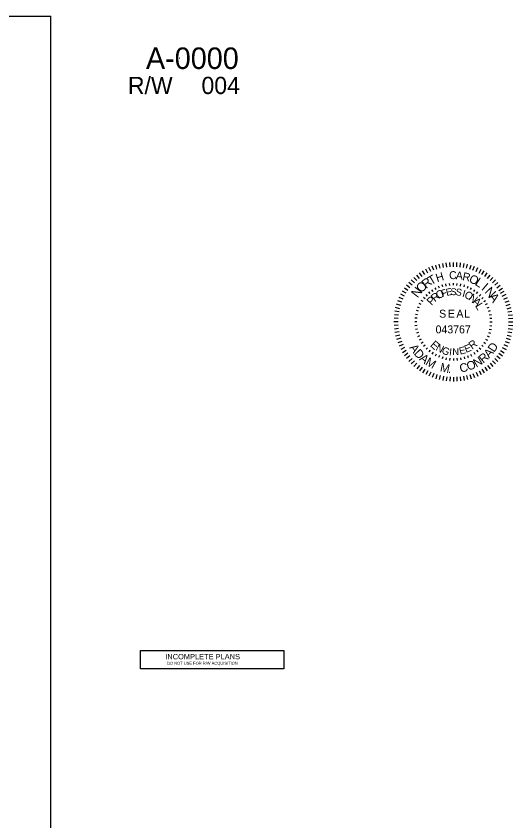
# Model space of a CAD drawing. Extents: x 24 to 2046, y 15 to 1115.
# Drawn here: x 1700 to 2046, y 554 to 1115 of the extents above; entities that cross this region are included whole.
import ezdxf

# ---------------------------------------------------------------- set-up
doc = ezdxf.new("R2010")
doc.units = 0
for name, color, linetype in [('Sheet_RDY_PE_Seal_Cell', 7, 'Continuous'), ('Sheet_Title_Block_Text', 7, 'Continuous'), ('z - Construction', 7, 'Continuous')]:
    doc.layers.add(name, color=color, linetype=linetype)

msp = doc.modelspace()

# ---------------------------------------------------------------- linework, layer by layer
at = {"layer": 'Sheet_RDY_PE_Seal_Cell'}
for p, q in [((23.95, 1114.98), (1723.95, 1114.98)), ((1723.95, 14.98), (1723.95, 1114.98)), ((1997.61, 939.67), (1997.07, 942.62)), ((1999.91, 940.02), (1999.55, 943)), ((2002.23, 940.23), (2002.04, 943.22)), ((2004.55, 940.3), (2004.55, 943.3)), ((2006.87, 940.23), (2007.05, 943.22)), ((2009.19, 940.02), (2009.55, 943)), ((2011.49, 939.67), (2012.03, 942.62)), ((1984.64, 934.75), (1983.09, 937.32)), ((1986.67, 935.89), (1985.27, 938.55)), ((1988.76, 936.91), (1987.53, 939.64)), ((1990.91, 937.8), (1989.84, 940.6)), ((1993.1, 938.56), (1992.21, 941.42)), ((1995.34, 939.18), (1994.62, 942.09)), ((2013.76, 939.18), (2014.48, 942.09)), ((2016, 938.56), (2016.89, 941.42)), ((2018.19, 937.8), (2019.26, 940.6)), ((2020.34, 936.91), (2021.57, 939.64)), ((2022.43, 935.89), (2023.82, 938.55)), ((2024.45, 934.75), (2026.01, 937.32)), ((1979.03, 930.62), (1977.04, 932.87)), ((1980.82, 932.11), (1978.97, 934.47)), ((1982.69, 933.49), (1980.99, 935.96)), ((2026.41, 933.49), (2028.11, 935.96)), ((2028.28, 932.11), (2030.13, 934.47)), ((2030.06, 930.62), (2032.05, 932.87)), ((1974.26, 925.55), (1971.9, 927.4)), ((1975.75, 927.34), (1973.51, 929.33)), ((1977.34, 929.03), (1975.22, 931.15)), ((1994.8, 925.37), (1994.22, 926.75)), ((1997.15, 926.21), (1996.72, 927.64)), ((1999.58, 926.82), (1999.28, 928.29)), ((2002.05, 927.18), (2001.91, 928.68)), ((2004.55, 927.31), (2004.55, 928.81)), ((2007.05, 927.18), (2007.19, 928.68)), ((2009.52, 926.82), (2009.82, 928.29)), ((2011.95, 926.21), (2012.38, 927.64)), ((2014.3, 925.37), (2014.88, 926.75)), ((2031.76, 929.03), (2033.88, 931.15)), ((2033.35, 927.34), (2035.59, 929.32)), ((2034.84, 925.55), (2037.2, 927.4)), ((1970.48, 919.7), (1967.82, 921.1)), ((1971.62, 921.73), (1969.05, 923.28)), ((1972.88, 923.68), (1970.42, 925.38)), ((1986.53, 919.84), (1985.47, 920.9)), ((1988.38, 921.52), (1987.43, 922.68)), ((1990.39, 923.01), (1989.56, 924.26)), ((1992.54, 924.3), (1991.83, 925.62)), ((2016.56, 924.3), (2017.27, 925.62)), ((2018.71, 923.01), (2019.54, 924.26)), ((2020.72, 921.52), (2021.67, 922.68)), ((2022.57, 919.84), (2023.63, 920.9)), ((2036.22, 923.68), (2038.68, 925.38)), ((2037.48, 921.73), (2040.04, 923.28)), ((2038.62, 919.7), (2041.27, 921.1)), ((1968.57, 915.47), (1965.77, 916.53)), ((1969.46, 917.61), (1966.73, 918.84)), ((1982.07, 913.84), (1980.75, 914.54)), ((1983.36, 915.98), (1982.11, 916.81)), ((1984.85, 917.99), (1983.69, 918.94)), ((2024.25, 917.99), (2025.41, 918.94)), ((2025.74, 915.98), (2026.99, 916.81)), ((2027.03, 913.84), (2028.35, 914.54)), ((2039.64, 917.61), (2042.37, 918.84)), ((2040.53, 915.47), (2043.33, 916.53)), ((1966.7, 908.76), (1963.75, 909.3)), ((1967.19, 911.03), (1964.28, 911.75)), ((1967.81, 913.27), (1964.95, 914.16)), ((1980.16, 909.22), (1978.73, 909.65)), ((1981, 911.57), (1979.62, 912.15)), ((2028.1, 911.57), (2029.48, 912.15)), ((2028.94, 909.22), (2030.37, 909.65)), ((2041.29, 913.27), (2044.15, 914.16)), ((2041.91, 911.03), (2044.82, 911.75)), ((2042.4, 908.76), (2045.35, 909.3)), ((1966.14, 904.14), (1963.15, 904.33)), ((1966.35, 906.46), (1963.38, 906.82)), ((1979.19, 904.32), (1977.7, 904.47)), ((1979.55, 906.79), (1978.08, 907.09)), ((2029.54, 906.79), (2031.02, 907.09)), ((2029.91, 904.32), (2031.4, 904.47)), ((2042.74, 906.46), (2045.72, 906.82)), ((2042.96, 904.14), (2045.95, 904.33)), ((1966.07, 901.82), (1963.07, 901.82)), ((1966.14, 899.5), (1963.15, 899.32)), ((1979.06, 901.82), (1977.57, 901.82)), ((1979.19, 899.32), (1977.7, 899.18)), ((2029.91, 899.32), (2031.4, 899.18)), ((2030.03, 901.82), (2031.53, 901.82)), ((2042.96, 899.5), (2045.95, 899.32)), ((2043.03, 901.82), (2046.02, 901.82)), ((1966.35, 897.18), (1963.38, 896.82)), ((1966.7, 894.89), (1963.75, 894.35)), ((1967.19, 892.61), (1964.28, 891.9)), ((1979.55, 896.85), (1978.08, 896.56)), ((1980.16, 894.42), (1978.73, 893.99)), ((1981, 892.07), (1979.62, 891.5)), ((2028.1, 892.07), (2029.48, 891.5)), ((2028.94, 894.42), (2030.37, 893.99)), ((2029.54, 896.85), (2031.02, 896.56)), ((2041.91, 892.61), (2044.82, 891.9)), ((2042.4, 894.89), (2045.35, 894.35)), ((2042.74, 897.19), (2045.72, 896.82)), ((1967.81, 890.38), (1964.95, 889.48)), ((1968.57, 888.18), (1965.77, 887.11)), ((1982.07, 889.81), (1980.75, 889.1)), ((1983.36, 887.66), (1982.11, 886.83)), ((2025.74, 887.66), (2026.99, 886.83)), ((2027.03, 889.81), (2028.35, 889.1)), ((2040.53, 888.18), (2043.33, 887.11)), ((2041.29, 890.37), (2044.15, 889.48)), ((1969.46, 886.03), (1966.73, 884.8)), ((1970.48, 883.94), (1967.82, 882.55)), ((1971.62, 881.91), (1969.05, 880.36)), ((1984.85, 885.66), (1983.69, 884.7)), ((1986.53, 883.8), (1985.47, 882.74)), ((1988.38, 882.12), (1987.43, 880.96)), ((2020.72, 882.12), (2021.67, 880.96)), ((2022.57, 883.8), (2023.63, 882.74)), ((2024.25, 885.66), (2025.41, 884.7)), ((2037.48, 881.91), (2040.04, 880.36)), ((2038.62, 883.94), (2041.28, 882.55)), ((2039.64, 886.03), (2042.37, 884.8)), ((1972.88, 879.97), (1970.42, 878.26)), ((1974.26, 878.09), (1971.9, 876.24)), ((1975.75, 876.31), (1973.51, 874.32)), ((1990.39, 880.63), (1989.56, 879.39)), ((1992.54, 879.35), (1991.83, 878.03)), ((1994.8, 878.28), (1994.22, 876.89)), ((1997.15, 877.43), (1996.71, 876)), ((1999.58, 876.83), (1999.28, 875.36)), ((2002.05, 876.46), (2001.91, 874.97)), ((2004.55, 876.34), (2004.55, 874.84)), ((2007.05, 876.46), (2007.19, 874.97)), ((2009.52, 876.83), (2009.82, 875.36)), ((2011.95, 877.43), (2012.38, 876)), ((2014.3, 878.28), (2014.88, 876.89)), ((2016.56, 879.35), (2017.27, 878.02)), ((2018.71, 880.63), (2019.54, 879.39)), ((2033.35, 876.31), (2035.59, 874.32)), ((2034.84, 878.09), (2037.2, 876.24)), ((2036.22, 879.97), (2038.68, 878.26)), ((1977.34, 874.61), (1975.22, 872.49)), ((1979.03, 873.02), (1977.04, 870.78)), ((1980.82, 871.53), (1978.97, 869.17)), ((1982.69, 870.16), (1980.99, 867.69)), ((2026.41, 870.16), (2028.11, 867.69)), ((2028.28, 871.53), (2030.13, 869.17)), ((2030.06, 873.02), (2032.05, 870.78)), ((2031.76, 874.61), (2033.88, 872.49)), ((1984.64, 868.89), (1983.09, 866.33)), ((1986.67, 867.75), (1985.27, 865.1)), ((1988.76, 866.73), (1987.53, 864)), ((1990.91, 865.85), (1989.84, 863.04)), ((1993.1, 865.09), (1992.21, 862.22)), ((1995.34, 864.46), (1994.62, 861.55)), ((1997.61, 863.98), (1997.07, 861.03)), ((2011.49, 863.98), (2012.03, 861.03)), ((2013.76, 864.46), (2014.48, 861.55)), ((2016, 865.09), (2016.89, 862.22)), ((2018.19, 865.85), (2019.26, 863.04)), ((2020.34, 866.73), (2021.57, 864)), ((2022.43, 867.75), (2023.82, 865.1)), ((2024.45, 868.89), (2026.01, 866.33)), ((1999.91, 863.63), (1999.55, 860.65)), ((2002.23, 863.42), (2002.04, 860.42)), ((2004.55, 863.35), (2004.55, 860.35)), ((2006.87, 863.41), (2007.05, 860.42)), ((2009.19, 863.63), (2009.55, 860.65))]:
    msp.add_line(p, q, dxfattribs=at)
at = {"layer": 'Sheet_Title_Block_Text'}
for centre in [(1813.51, 1085.6), (1788.51, 1066.64), (1838.51, 1066.64)]:
    msp.add_circle(centre, 0.06, dxfattribs=at)
at = {"layer": 'z - Construction'}
msp.add_lwpolyline([(1786.44, 672.68), (1886.44, 672.68), (1886.44, 659.94), (1786.44, 659.94)], close=True, dxfattribs=at)

# ---------------------------------------------------------------- texts
at = {"layer": 'Sheet_RDY_PE_Seal_Cell'}
for s, height, rotation, p in [('C', 5.5, 2.964, (2001.72, 931.5)), ('A', 5.51, 355.8747, (2006.08, 931.57)), ('R', 6.3, 38.4101, (1985.49, 924.72)), ('T', 6.13, 31.3209, (1989.04, 927.24)), ('H', 5.73, 17.1424, (1993.21, 929.49)), ('R', 5.6, 348.7855, (2010.54, 930.99)), ('O', 5.96, 334.607, (2014.9, 929.87)), ('L', 6.16, 327.5178, (2019.06, 927.89)), ('N', 6.4, 52.5886, (1979.56, 918.17)), ('O', 6.4, 45.4993, (1982.24, 921.61)), ('I', 6.32, 320.4286, (2023.68, 924.65)), ('N', 6.41, 313.3394, (2025.95, 922.54)), ('R', 5.53, 40.0942, (1991.71, 915.38)), ('O', 5.39, 33.0621, (1994.35, 917.43)), ('F', 5.04, 18.9979, (1996.71, 918.84)), ('E', 4.9, 11.9657, (1999.87, 919.88)), ('S', 4.8, 357.9015, (2002.38, 920.55)), ('S', 4.86, 350.8694, (2005.8, 920.5)), ('I', 4.98, 343.8373, (2010.4, 919.53)), ('O', 5.32, 329.773, (2011.62, 919.28)), ('N', 5.48, 322.7409, (2014.65, 917.56)), ('A', 6.39, 306.2501, (2028.75, 919.19)), ('P', 5.6, 47.1264, (1989.39, 912.89)), ('A', 5.58, 315.7088, (2017.25, 915.47)), ('L', 5.51, 301.6445, (2019.45, 912.97)), ('S', 5.5, 0, (1994.61, 904.78)), ('E', 5.5, 0, (2000.7, 904.83)), ('A', 5.5, 0, (2006.66, 904.81)), ('L', 5.5, 0, (2011.98, 904.83)), ('043767', 5.497, 0, (1992.12, 893.86)), ('E', 5.55, 318.5439, (1987.97, 885.17)), ('N', 5.25, 332.6082, (1991.73, 882.25)), ('E', 5.11, 21.833, (2013.34, 880.18)), ('R', 5.45, 35.8972, (2017.57, 882.41)), ('D', 5.96, 57.0216, (2032.99, 880.22)), ('A', 5.96, 304.3883, (1973.66, 883.88)), ('D', 5.96, 312.8877, (1976.65, 879.51)), ('G', 5.07, 339.6403, (1995.92, 880.02)), ('I', 4.83, 353.7045, (2001.43, 878.59)), ('N', 4.8, 0.7366, (2003.85, 878.64)), ('E', 4.95, 14.8009, (2009.24, 878.94)), ('A', 5.96, 48.5222, (2029.49, 876.25)), ('A', 5.96, 321.7161, (1980.4, 875.5)), ('M', 5.96, 330.2155, (1984.56, 872.22)), ('N', 5.96, 30.8653, (2020.56, 869.89)), ('R', 5.96, 39.6937, (2025.27, 872.72)), ('M', 5.96, 348.5245, (1994.87, 867.44)), ('C', 5.96, 12.2306, (2009.51, 866.45)), ('O', 5.96, 21.3847, (2015.08, 867.69)), ('.', 5.96, 358.0052, (2000.67, 866.31))]:
    msp.add_text(s, height=height, rotation=rotation, dxfattribs=at).set_placement(p)
at = {"layer": 'Sheet_Title_Block_Text'}
for s, height, p in [('A-0000', 15, (1790.24, 1078.1)), ('R/W', 12, (1777.66, 1060.64)), ('004', 12, (1828.95, 1060.64))]:
    msp.add_text(s, height=height, dxfattribs=at).set_placement(p)
at = {"layer": 'z - Construction'}
for s, height, p in [('INCOMPLETE PLANS', 3.75, (1803.71, 666.61)), ('DO NOT USE FOR R/W ACQUISITION', 2.025, (1804.97, 662.84))]:
    msp.add_text(s, height=height, dxfattribs=at).set_placement(p)

doc.saveas('drawing.dxf')
